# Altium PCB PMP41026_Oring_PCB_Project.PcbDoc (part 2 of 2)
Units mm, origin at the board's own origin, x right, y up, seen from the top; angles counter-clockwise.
Board outline 34.25 x 35.26 mm, 8 copper layers (Top Layer, Layer 2, Layer 3, Layer 4, Layer 5, Layer 6, Layer 7, Bottom Layer), stack 1.271 mm thick; 34 components, 15 nets, 290 pads, 1015 vias.
Unrouted connection lines stored in the file: 1.
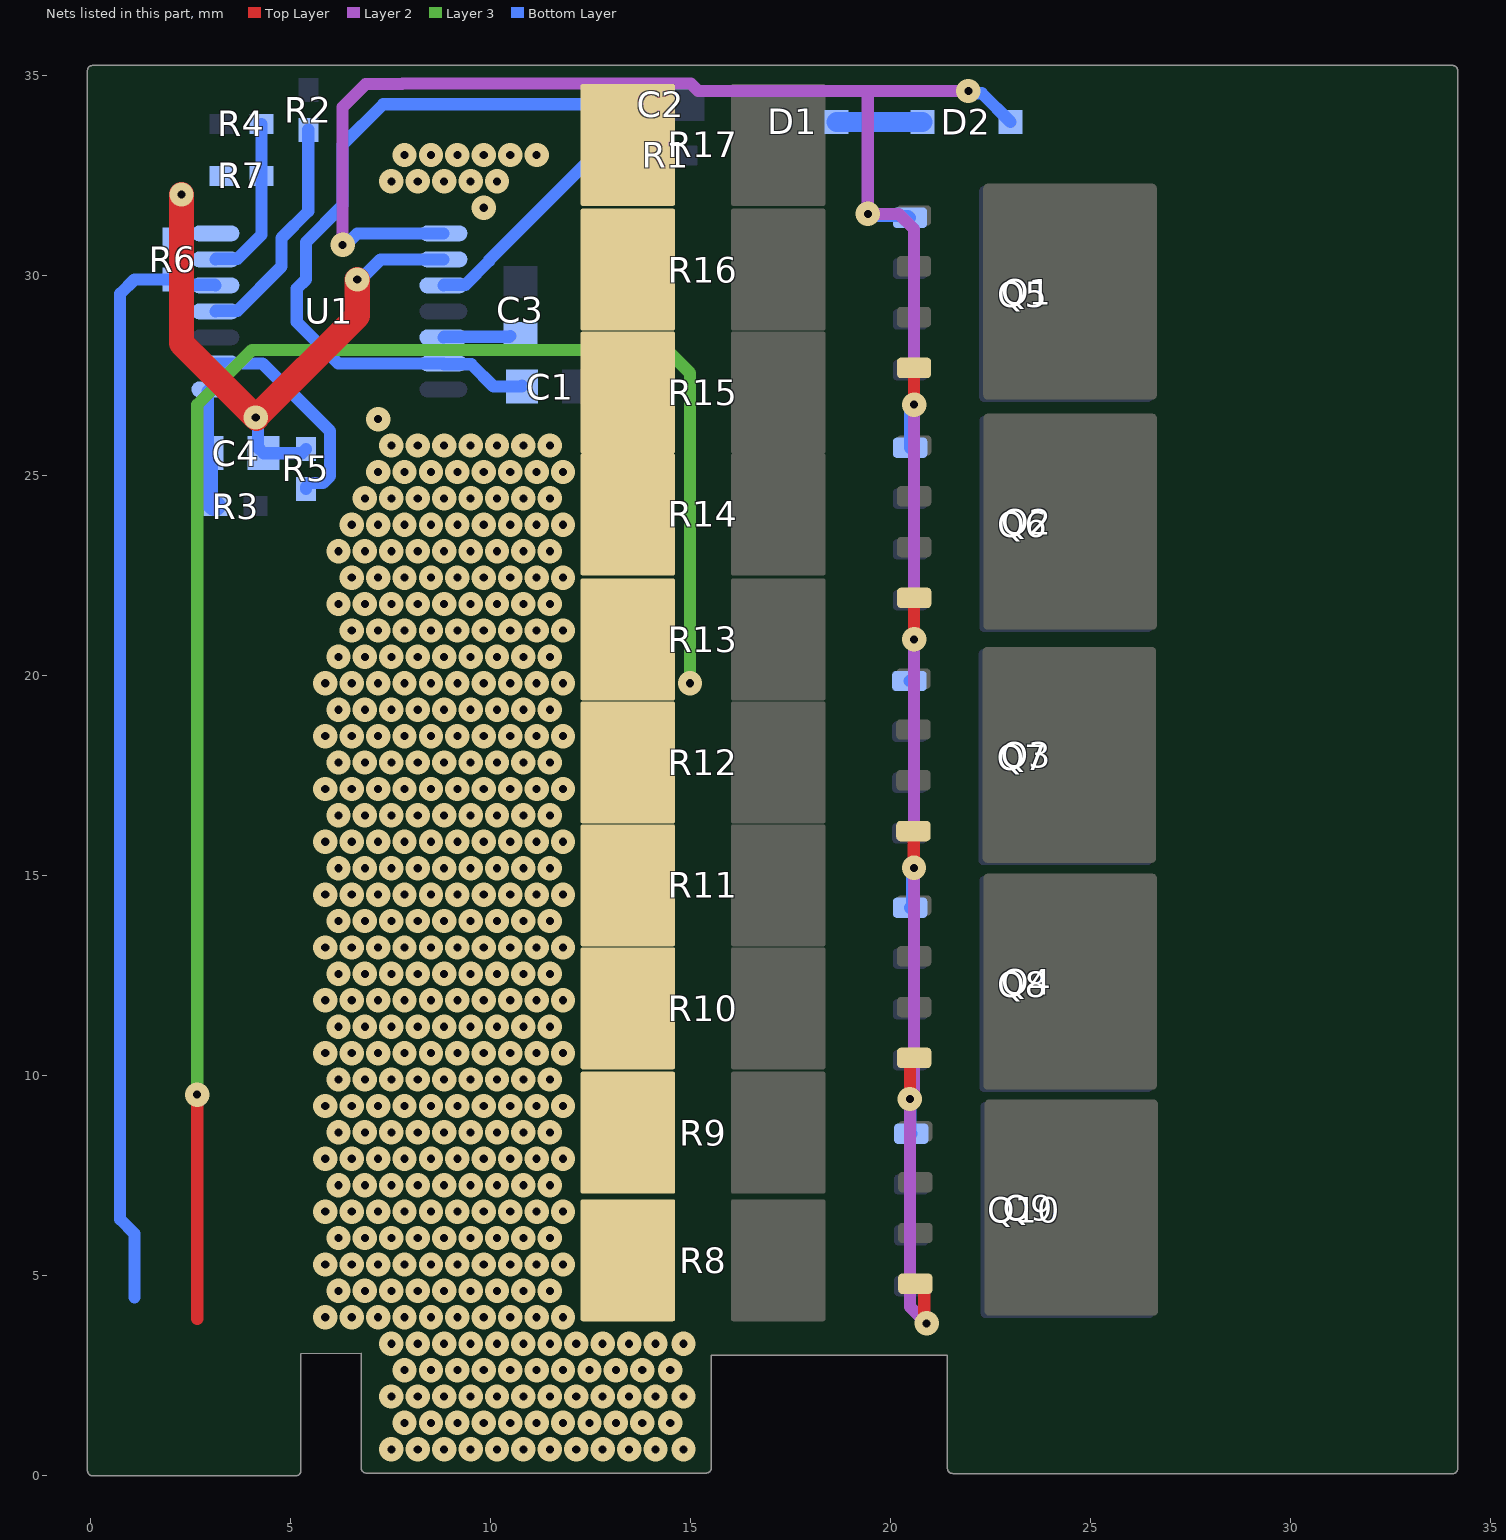
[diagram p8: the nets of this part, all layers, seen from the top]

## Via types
v1: diameter 0.61, hole 0.203, Top Layer to Bottom Layer, 996 vias
v2: diameter 0.61, hole 0.203, Top Layer to Bottom Layer, tented both sides, 18 vias
v3: diameter 0.508, hole 0.254, Top Layer to Bottom Layer, 1 vias

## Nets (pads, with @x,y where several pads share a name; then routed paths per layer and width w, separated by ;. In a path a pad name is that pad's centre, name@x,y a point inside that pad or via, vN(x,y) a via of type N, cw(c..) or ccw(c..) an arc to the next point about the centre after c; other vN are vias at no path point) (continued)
Iout_SNS: R8.1 R9.1 R10.1 R11.1 R12.1 R13.1 R14.1 R15.1 R16.1 R17.1 | length 43.7
  Top Layer w0.305: 2.664,3.927 v2(2.664,9.527)
  Layer 3 w0.305: v2(2.664,9.527) 2.664,26.776 4.035,28.146 14.41,28.146 14.986,27.57 v2(14.986,19.812)
  other v1: 7.518,0.66 8.179,0.66 8.839,0.66 9.5,0.66 10.16,0.66 10.82,0.66 11.481,0.66 12.141,0.66 12.802,0.66 13.462,0.66 14.122,0.66 14.822,0.66 7.849,1.321 8.509,1.321 9.169,1.321 9.83,1.321 10.49,1.321 11.151,1.321 11.811,1.321 12.471,1.321 13.132,1.321 13.792,1.321 14.492,1.321 7.518,1.981 8.179,1.981 8.839,1.981 9.5,1.981 10.16,1.981 10.82,1.981 11.481,1.981 12.141,1.981 12.802,1.981 13.462,1.981 14.122,1.981 14.822,1.981 7.849,2.642 8.509,2.642 9.169,2.642 9.83,2.642 10.49,2.642 11.151,2.642 11.811,2.642 12.471,2.642 13.132,2.642 13.792,2.642 14.492,2.642 7.518,3.302 8.179,3.302 8.839,3.302 9.5,3.302 10.16,3.302 10.82,3.302 11.481,3.302 12.141,3.302 12.802,3.302 13.462,3.302 14.122,3.302 14.822,3.302 5.867,3.962 6.528,3.962 7.188,3.962 7.849,3.962 8.509,3.962 9.169,3.962 9.83,3.962 10.49,3.962 11.151,3.962 11.811,3.962 6.198,4.623 6.858,4.623 7.518,4.623 8.179,4.623 8.839,4.623 9.5,4.623 10.16,4.623 10.82,4.623 11.481,4.623 5.867,5.283 6.528,5.283 7.188,5.283 7.849,5.283 8.509,5.283 9.169,5.283 9.83,5.283 10.49,5.283 11.151,5.283 11.811,5.283 6.198,5.944 6.858,5.944 7.518,5.944 8.179,5.944 8.839,5.944 9.5,5.944 10.16,5.944 10.82,5.944 11.481,5.944 5.867,6.604 6.528,6.604 7.188,6.604 7.849,6.604 8.509,6.604 9.169,6.604 9.83,6.604 10.49,6.604 11.151,6.604 11.811,6.604 6.198,7.264 6.858,7.264 7.518,7.264 8.179,7.264 8.839,7.264 9.5,7.264 10.16,7.264 10.82,7.264 11.481,7.264 5.867,7.925 6.528,7.925 7.188,7.925 7.849,7.925 8.509,7.925 9.169,7.925 9.83,7.925 10.49,7.925 11.151,7.925 11.811,7.925 6.198,8.585 6.858,8.585 7.518,8.585 8.179,8.585 8.839,8.585 9.5,8.585 10.16,8.585 10.82,8.585 11.481,8.585 5.867,9.246 6.528,9.246 7.188,9.246 7.849,9.246 8.509,9.246 9.169,9.246 9.83,9.246 10.49,9.246 11.151,9.246 11.811,9.246 6.198,9.906 6.858,9.906 7.518,9.906 8.179,9.906 8.839,9.906 9.5,9.906 10.16,9.906 10.82,9.906 11.481,9.906 5.867,10.566 6.528,10.566 7.188,10.566 7.849,10.566 8.509,10.566 9.169,10.566 9.83,10.566 10.49,10.566 11.151,10.566 11.811,10.566 6.198,11.227 6.858,11.227 7.518,11.227 8.179,11.227 8.839,11.227 9.5,11.227 10.16,11.227 10.82,11.227 11.481,11.227 5.867,11.887 6.528,11.887 7.188,11.887 7.849,11.887 8.509,11.887 9.169,11.887 9.83,11.887 10.49,11.887 11.151,11.887 11.811,11.887 6.198,12.548 6.858,12.548 7.518,12.548 8.179,12.548 8.839,12.548 9.5,12.548 10.16,12.548 10.82,12.548 11.481,12.548 5.867,13.208 6.528,13.208 7.188,13.208 7.849,13.208 8.509,13.208 9.169,13.208 9.83,13.208 10.49,13.208 11.151,13.208 11.811,13.208 6.198,13.868 6.858,13.868 7.518,13.868 8.179,13.868 8.839,13.868 9.5,13.868 10.16,13.868 10.82,13.868 11.481,13.868 5.867,14.529 6.528,14.529 7.188,14.529 7.849,14.529 8.509,14.529 9.169,14.529 9.83,14.529 10.49,14.529 11.151,14.529 11.811,14.529 6.198,15.189 6.858,15.189 7.518,15.189 8.179,15.189 8.839,15.189 9.5,15.189 10.16,15.189 10.82,15.189 11.481,15.189 5.867,15.85 6.528,15.85 7.188,15.85 7.849,15.85 8.509,15.85 9.169,15.85 9.83,15.85 10.49,15.85 11.151,15.85 11.811,15.85 6.198,16.51 6.858,16.51 7.518,16.51 8.179,16.51 8.839,16.51 9.5,16.51 10.16,16.51 10.82,16.51 11.481,16.51 5.867,17.17 6.528,17.17 7.188,17.17 7.849,17.17 8.509,17.17 9.169,17.17 9.83,17.17 10.49,17.17 11.151,17.17 11.811,17.17 6.198,17.831 6.858,17.831 7.518,17.831 8.179,17.831 8.839,17.831 9.5,17.831 10.16,17.831 10.82,17.831 11.481,17.831 5.867,18.491 6.528,18.491 7.188,18.491 7.849,18.491 8.509,18.491 9.169,18.491 9.83,18.491 10.49,18.491 11.151,18.491 11.811,18.491 6.198,19.152 6.858,19.152 7.518,19.152 8.179,19.152 8.839,19.152 9.5,19.152 10.16,19.152 10.82,19.152 11.481,19.152 5.867,19.812 6.528,19.812 7.188,19.812 7.849,19.812 8.509,19.812 9.169,19.812 9.83,19.812 10.49,19.812 11.151,19.812 11.811,19.812 6.198,20.472 6.858,20.472 7.518,20.472 8.179,20.472 8.839,20.472 9.5,20.472 10.16,20.472 10.82,20.472 11.481,20.472 6.528,21.133 7.188,21.133 7.849,21.133 8.509,21.133 9.169,21.133 9.83,21.133 10.49,21.133 11.151,21.133 11.811,21.133 6.198,21.793 6.858,21.793 7.518,21.793 8.179,21.793 8.839,21.793 9.5,21.793 10.16,21.793 10.82,21.793 11.481,21.793 6.528,22.454 7.188,22.454 7.849,22.454 8.509,22.454 9.169,22.454 9.83,22.454 10.49,22.454 11.151,22.454 11.811,22.454 6.198,23.114 6.858,23.114 7.518,23.114 8.179,23.114 8.839,23.114 9.5,23.114 10.16,23.114 10.82,23.114 11.481,23.114 6.528,23.774 7.188,23.774 7.849,23.774 8.509,23.774 9.169,23.774 9.83,23.774 10.49,23.774 11.151,23.774 11.811,23.774 6.858,24.435 7.518,24.435 8.179,24.435 8.839,24.435 9.5,24.435 10.16,24.435 10.82,24.435 11.481,24.435 7.188,25.095 7.849,25.095 8.509,25.095 9.169,25.095 9.83,25.095 10.49,25.095 11.151,25.095 11.811,25.095 7.518,25.756 8.179,25.756 8.839,25.756 9.5,25.756 10.16,25.756 10.82,25.756 11.481,25.756 7.188,26.416 9.83,31.699 7.518,32.36 8.179,32.36 8.839,32.36 9.5,32.36 10.16,32.36 7.849,33.02 8.509,33.02 9.169,33.02 9.83,33.02 10.49,33.02 11.151,33.02
NetC1_1: C1.1 C2.2 U1.13 | length 18.9
  Bottom Layer w0.305: C1.1@10.785,27.256 C1.1@10.785,27.231 10.073,27.231 9.515,27.79 8.838,27.79 U1.13@8.82,27.808 6.194,27.808 5.156,28.845 5.156,29.681 5.384,29.909 5.384,30.84 6.299,31.756 6.299,33.274 7.315,34.29 C2.2@13.549,34.29
NetC3_2: C3.2 U1.12 | length 1.7
  Bottom Layer w0.305: U1.12@8.82,28.458 8.838,28.476 10.469,28.476 C3.2@10.49,28.497
NetC4_1: C4.1 R3.1 U1.1 | length 3.2
  Bottom Layer w0.305: C4.1@2.928,25.565 2.928,27.114 2.972,27.158 U1.1@3.12,27.158
  Bottom Layer w0.508: C4.1@2.928,25.565 2.928,24.402 3.086,24.244 R3.1@3.128,24.244
NetD1_1: D1.1 D2.1 | length 2.1
  Bottom Layer w0.508: D1.1@18.651,33.845 D2.1@20.795,33.845
NetR1_1: R1.1 U1.10 | length 6.4
  Bottom Layer w0.305: U1.10@8.82,29.758 8.838,29.776 9.37,29.776 9.967,30.373 9.967,30.392 12.582,33.007 R1.1@13.876,33.007
NetR2_1: R2.1 U1.4 | length 5.8
  Bottom Layer w0.305: U1.4@3.12,29.108 3.138,29.126 3.67,29.126 4.775,30.232 4.775,30.945 5.443,31.613 R2.1@5.443,33.65
NetR4_1: R4.1 R7.2 U1.6 | length 4.2
  Bottom Layer w0.305: U1.6@3.12,30.408 3.138,30.426 3.67,30.426 4.27,31.027 R7.2@4.27,32.495 R4.1@4.27,33.795
NetR5_2: R5.2 U1.2 | length 5.5
  Bottom Layer w0.305: U1.2@3.12,27.808 4.296,27.808 5.986,26.117 5.986,24.998 5.808,24.819 5.482,24.819 5.384,24.721 R5.2@5.384,24.671
ORing_CTRL: R6.2 U1.5 | length 27.8
  Bottom Layer w0.305: 1.096,4.465 1.096,6.053 0.739,6.41 0.739,29.551 1.096,29.908 2.014,29.908 2.146,29.776 3.102,29.776 U1.5@3.12,29.758
ORing_Gate: D2.2 Q1.4 Q2.4 Q3.4 Q4.4 Q5.4 Q6.4 Q7.4 Q8.4 Q9.4 Q10.4 U1.8 | length 65.8
  Top Layer w0.305: v2(20.482,9.42) 20.482,10.345 20.585,10.448 Q4.4@20.589,10.448 ; Q3.4@20.571,16.118 20.579,16.11 20.579,15.206 v2(20.586,15.198) ; Q1.4@20.586,27.698 20.587,27.696 20.587,26.78 v2(20.589,26.778) ; v2(20.589,20.909) Q2.4@20.589,21.948 ; Q9.4@20.619,4.799 20.739,4.799 20.841,4.697 20.841,3.868 v2(20.9,3.81)
  Layer 2 w0.305: v2(6.299,30.772) 6.299,34.216 6.874,34.79 7.788,34.79 7.805,34.807 15.002,34.807 15.189,34.62 19.431,34.62 ; v2(20.9,3.81) 20.482,4.228 v2(20.482,9.42) 20.482,9.503 20.586,9.607 v2(20.586,15.198) 20.587,15.2 20.587,20.907 v2(20.589,20.909) v2(20.589,26.778) 20.589,31.161 20.204,31.547 v2(19.431,31.547) 19.431,34.62 ; v2(21.946,34.62) 19.431,34.62
  Bottom Layer w0.305: v2(6.299,30.772) 6.382,30.772 6.668,31.058 U1.8@8.82,31.058 ; v2(19.431,31.547) 19.48,31.498 20.436,31.498 Q5.4@20.484,31.449 ; Q7.4@20.469,19.869 20.486,19.869 20.589,19.972 v2(20.589,20.909) ; v2(20.482,9.42) 20.499,9.403 20.499,8.568 Q10.4@20.517,8.551 ; Q8.4@20.487,14.199 20.537,14.248 20.537,15.149 v2(20.586,15.198) ; Q6.4@20.487,25.699 20.487,26.594 20.589,26.696 v2(20.589,26.778) ; v2(21.946,34.62) 22.004,34.562 22.278,34.562 D2.2@22.995,33.845
SGND: C4.2 R5.1 R6.1 R7.1 U1.7 U1.9 | length 15.4
  Top Layer w0.305: v2@6.61,29.966 v2(6.668,29.908)
  Top Layer w0.635: v2(2.273,32.031) 2.273,28.313 v2(4.128,26.458) ; v2@4.149,26.438 v2(4.128,26.458) ; v2(6.668,29.908) 6.668,28.997 v2(4.128,26.458)
  Bottom Layer w0.305: v2(4.128,26.458) 4.187,26.4 4.187,25.707 C4.2@4.328,25.565 5.286,25.565 5.384,25.662 R5.1@5.384,25.671 ; v2(6.668,29.908) 6.745,29.908 7.245,30.408 U1.9@8.82,30.408
pads on no net: Q1.9@22.576,27.23 Q1.9@22.576,31.975 Q1.9@22.871,28.273 Q1.9@22.871,29.603 Q1.9@22.871,30.933 Q1.9@24.021,28.273 Q1.9@24.021,29.603 Q1.9@24.021,30.933 Q1.9@24.156,29.603 Q1.9@25.171,28.273 Q1.9@25.171,29.603 Q1.9@25.171,30.933 Q2.9@22.579,21.48 Q2.9@22.579,26.225 Q2.9@22.874,22.523 Q2.9@22.874,23.853 Q2.9@22.874,25.183 Q2.9@24.024,22.523 Q2.9@24.024,23.853 Q2.9@24.024,25.183 Q2.9@24.159,23.853 Q2.9@25.174,22.523 Q2.9@25.174,23.853 Q2.9@25.174,25.183 Q3.9@22.561,15.65 Q3.9@22.561,20.395 Q3.9@22.856,16.693 Q3.9@22.856,18.023 Q3.9@22.856,19.353 Q3.9@24.006,16.693 Q3.9@24.006,18.023 Q3.9@24.006,19.353 Q3.9@24.141,18.023 Q3.9@25.156,16.693 Q3.9@25.156,18.023 Q3.9@25.156,19.353 Q4.9@22.579,9.98 Q4.9@22.579,14.725 Q4.9@22.874,11.023 Q4.9@22.874,12.353 Q4.9@22.874,13.683 Q4.9@24.024,11.023 Q4.9@24.024,12.353 Q4.9@24.024,13.683 Q4.9@24.159,12.353 Q4.9@25.174,11.023 Q4.9@25.174,12.353 Q4.9@25.174,13.683 Q5.9@22.474,27.172 Q5.9@22.474,31.917 Q5.9@22.769,28.214 Q5.9@22.769,29.544 Q5.9@22.769,30.874 Q5.9@23.919,28.214 Q5.9@23.919,29.544 Q5.9@23.919,30.874 Q5.9@24.054,29.544 Q5.9@25.069,28.214 Q5.9@25.069,29.544 Q5.9@25.069,30.874 Q6.9@22.477,21.422 Q6.9@22.477,26.167 Q6.9@22.772,22.464 Q6.9@22.772,23.794 Q6.9@22.772,25.124 Q6.9@23.922,22.464 Q6.9@23.922,23.794 Q6.9@23.922,25.124 Q6.9@24.057,23.794 Q6.9@25.072,22.464 Q6.9@25.072,23.794 Q6.9@25.072,25.124 Q7.9@22.459,15.592 Q7.9@22.459,20.337 Q7.9@22.754,16.634 Q7.9@22.754,17.964 Q7.9@22.754,19.294 Q7.9@23.904,16.634 Q7.9@23.904,17.964 Q7.9@23.904,19.294 Q7.9@24.039,17.964 Q7.9@25.054,16.634 Q7.9@25.054,17.964 Q7.9@25.054,19.294 Q8.9@22.477,9.922 Q8.9@22.477,14.667 Q8.9@22.772,10.964 Q8.9@22.772,12.294 Q8.9@22.772,13.624 Q8.9@23.922,10.964 Q8.9@23.922,12.294 Q8.9@23.922,13.624 Q8.9@24.057,12.294 Q8.9@25.072,10.964 Q8.9@25.072,12.294 Q8.9@25.072,13.624 Q9.9@22.609,4.332 Q9.9@22.609,9.077 Q9.9@22.904,5.374 Q9.9@22.904,6.704 Q9.9@22.904,8.034 Q9.9@24.054,5.374 Q9.9@24.054,6.704 Q9.9@24.054,8.034 Q9.9@24.189,6.704 Q9.9@25.204,5.374 Q9.9@25.204,6.704 Q9.9@25.204,8.034 Q10.9@22.507,4.273 Q10.9@22.507,9.018 Q10.9@22.802,5.316 Q10.9@22.802,6.646 Q10.9@22.802,7.976 Q10.9@23.952,5.316 Q10.9@23.952,6.646 Q10.9@23.952,7.976 Q10.9@24.087,6.646 Q10.9@25.102,5.316 Q10.9@25.102,6.646 Q10.9@25.102,7.976 U1.3 U1.14

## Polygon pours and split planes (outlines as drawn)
SGND on Layer 5 "SGND" (solid, remove dead copper, pour order 85): 1.27,32.512 0.254,31.496 0.254,13.112 3.649,9.718 3.649,5.072 4.149,4.572 4.395,4.572 4.649,4.826 4.649,26.388 7.091,28.83 7.091,29.966 6.991,29.966 4.445,32.512
Iout_SNS on Layer 5 "LAYER_5_IOUT_SNS_P055" (solid, remove dead copper, pour order 55): 14.904,3.658 15.426,3.136 15.5,3.136 15.5,0.185 15.49,0.195 13,0.16 6.891,0.2 6.891,3.187 5.131,3.187 5.131,34.738 5.523,35.13 14.904,35.13 14.904,20.574 14.471,20.141 14.471,19.483 14.904,19.05
12VB on Layer 5 "LAYER_5_12VB_P069" (solid, remove dead copper, pour order 69): 21.946,3.946 21.5,3.5 21.5,0.249 21.588,0.16 24.33,0.185 34.049,0.185 34.049,33.089 32.049,35.089 21.946,35.13
12VA on Layer 5 "LAYER_5_12VA_P074" (solid, remove dead copper, pour order 74): 15.57,4.066 16.5,3.152 21.256,3.148 21.26,3.683 21.209,3.734 21.285,3.81 21.285,35.126 15.57,35.179 15.57,19.812 16.153,19.229 16.153,18.617 15.57,18.034
no net on Top Solder "NONET_L-01_P-001" (solid): 6.891,3.211 6.891,0.2 15.391,0.145 15.391,3.185
no net on Top Solder "NONET_L-01_P-001" (solid): 21.549,3.324 21.549,0.185 32.065,0.185 32.034,3.324
no net on Top Solder "NONET_L-01_P-001" (solid): 0.049,3.187 5.105,3.187 5.105,0.197 5.131,0.171 0.049,0.171
no net on Top Solder "NONET_L-01_P-001" (solid): 7.518,35.13 7.518,24.645 5.131,22.258 5.131,4.06 6.07,3.121 6.891,3.121 6.891,0.197 6.941,0.146 14.561,0.146 14.561,3.708 12.167,3.708 12.141,3.683 12.116,3.708 12.116,35.179
no net on Top Solder "NONET_L-01_P-001" (solid): 23.038,32.563 23.241,32.36 27,32.36 27,3.324 26.811,3.135 24.018,3.135 24.018,0.178 34.049,0.187 34.049,33.089 32.008,35.13 23.038,35.13
SGND on Bottom Layer "BOTTOM_LAYER_SGND_P041" (solid, remove dead copper, pour order 41): 1.391,30.539 1.4,30.53 3.774,30.53 3.774,33.053 3.75,33.077 1.905,33.077 1.391,32.563
Iout_SNS on Bottom Layer "BOTTOM_LAYER_IOUT_SNS_P058" (solid, remove dead copper, pour order 58): 14.904,3.888 15.391,3.4 15.391,0.237 15.302,0.147 14.471,0.147 6.891,0.197 6.891,3.184 5.131,3.184 5.131,26.092 14.904,26.092 14.904,20.574 14.308,19.978 14.308,19.122 14.904,18.525
12VA on Bottom Layer "BOTTOM_LAYER_12VA_P077" (solid, remove dead copper, pour order 77): 15.57,4.066 16.5,3.152 21.256,3.148 21.26,3.683 21.209,3.734 21.285,3.81 21.285,35.126 15.57,35.179 15.57,19.812 16.122,19.26 16.122,18.798 15.57,18.246
12VB on Bottom Layer "BOTTOM_LAYER_12VB_P072" (solid, remove dead copper, pour order 72): 21.946,3.946 21.5,3.5 21.5,0.211 21.565,0.146 21.615,0.197 24.3,0.185 34.049,0.185 34.049,33.089 32.049,35.089 21.946,35.13
SGND on Layer 6 "SGND" (solid, remove dead copper, pour order 83): 1.27,32.512 0.254,31.496 0.254,13.112 3.649,9.718 3.649,5.072 4.149,4.572 4.395,4.572 4.649,4.826 4.649,26.388 7.091,28.83 7.091,29.966 6.991,29.966 4.445,32.512
Iout_SNS on Layer 6 "LAYER_6_IOUT_SNS_P056" (solid, remove dead copper, pour order 56): 14.904,3.732 15.5,3.136 15.5,0.411 15.24,0.151 14.471,0.151 6.891,0.2 6.891,3.187 5.131,3.187 5.131,34.738 5.523,35.13 14.904,35.13 14.904,20.574 14.521,20.191 14.521,19.433 14.904,19.05
12VB on Layer 6 "LAYER_6_12VB_P070" (solid, remove dead copper, pour order 70): 21.946,4.6 21.5,4.154 21.5,0.185 21.503,0.183 24.5,0.185 34.049,0.185 34.049,33.089 32.049,35.089 21.946,35.13
12VA on Layer 6 "LAYER_6_12VA_P075" (solid, remove dead copper, pour order 75): 16.5,3.152 15.57,4.082 15.57,18.034 16.256,18.72 16.256,19.229 15.57,19.915 15.57,35.179 21.285,35.126 21.285,3.81 21.209,3.734 21.26,3.683 21.256,3.148
no net on Bottom Solder "NONET_L-01_P-001" (solid): 0.049,3.187 5.131,3.187 5.131,0.171 0.049,0.171
no net on Bottom Solder "NONET_L-01_P-001" (solid): 0.102,5.639 4.801,5.639 4.801,2.669 4.828,2.642 4.438,2.252 0.049,2.252
no net on Bottom Solder "NONET_L-01_P-001" (solid): 6.891,3.211 6.891,0.2 15.391,0.145 15.391,3.185
no net on Bottom Solder "NONET_L-01_P-001" (solid): 21.549,3.324 21.549,0.185 32.065,0.185 32.034,3.324
no net on Bottom Solder "NONET_L-01_P-001" (solid): 7.518,26.149 7.518,24.739 5.131,22.351 5.131,4.154 6.07,3.215 6.891,3.215 6.891,0.29 6.941,0.24 14.561,0.24 14.561,3.802 14.561,26.224
no net on Bottom Solder "NONET_L-01_P-001" (solid): 24.049,32.457 27.03,32.457 27.03,3.422 26.841,3.233 24.049,3.233 24.049,0.276 34.049,0.285 34.049,33.217 32.038,35.228 24.049,35.228
no net on Bottom Solder "NONET_L-01_P-001" (solid): 15.57,30.772 15.57,3.136 15.586,3.121 19.736,3.121 19.736,30.772
SGND on Top Layer "SGND" (solid, remove dead copper, pour order 79): 1.27,32.512 0.254,31.496 0.254,13.112 3.649,9.718 3.649,2.286 4.649,2.286 4.649,26.388 7.091,28.83 7.091,29.966 6.991,29.966 4.445,32.512
Iout_SNS on Top Layer "TOP_LAYER_IOUT_SNS_P051" (solid, remove dead copper, pour order 51): 6.891,0.2 15.391,0.195 15.391,3.212 14.904,3.693 14.904,35.13 5.523,35.13 5.131,34.738 5.131,3.187 6.891,3.187
12VA on Top Layer "TOP_LAYER_12VA_P059" (solid, remove dead copper, pour order 59): 15.57,4.089 16.5,3.151 20.616,3.141 21.285,3.81 21.285,35.126 15.57,35.179
12VB on Top Layer "TOP_LAYER_12VB_P063" (solid, remove dead copper, pour order 63): 21.946,4.623 21.549,4.227 21.549,0.184 21.551,0.183 24.359,0.185 34.049,0.185 34.049,33.089 32.049,35.089 21.946,35.13
Iout_SNS on Layer 2 "LAYER_2_IOUT_SNS_P052" (solid, remove dead copper, pour order 52): 14.904,20.574 14.471,20.141 14.471,19.455 14.904,19.022 14.904,18.838 14.904,3.836 15.391,3.349 15.391,0.145 6.891,0.2 6.891,3.187 5.131,3.187 4.509,3.81 0.508,3.81 0.254,4.064 0.254,28.217 0.993,28.956 5.131,28.954 5.131,34.738 5.523,35.13 14.904,35.13
12VA on Layer 2 "LAYER_2_12VA_P062" (solid, remove dead copper, pour order 62): 15.57,4.066 16.5,3.152 21.256,3.148 21.26,3.683 21.209,3.734 21.285,3.81 21.285,35.126 15.57,35.179 15.57,19.812 16.256,19.126 16.256,18.796 15.582,18.122 15.57,18.034
12VB on Layer 2 "LAYER_2_12VB_P066" (solid, remove dead copper, pour order 66): 21.946,4.623 21.5,4.177 21.5,0.234 21.551,0.183 24.5,0.185 34.049,0.185 34.049,33.089 32.049,35.089 21.946,35.13
Iout_SNS on Layer 3 "LAYER_3_IOUT_SNS_P053" (solid, remove dead copper, pour order 53): 14.561,4.161 15.391,3.331 15.391,0.24 15.346,0.195 13,0.16 6.891,0.2 6.891,3.187 5.131,3.187 5.131,27.61 14.561,27.61
12VA on Layer 3 "LAYER_3_12VA_P064" (solid, remove dead copper, pour order 64): 15.57,4.088 16.527,3.131 17,3.151 21.256,3.148 21.26,3.683 21.209,3.734 21.285,3.81 21.285,35.126 16.256,35.173 16.256,19.229 16.256,18.508 15.57,17.822
12VB on Layer 3 "LAYER_3_12VB_P067" (solid, remove dead copper, pour order 67): 21.946,3.946 21.5,3.5 21.5,0.185 21.515,0.2 24.33,0.185 34.049,0.185 34.049,33.089 32.049,35.089 21.946,35.13
Iout_SNS on Layer 4 "LAYER_4_IOUT_SNS_P054" (solid, remove dead copper, pour order 54): 14.904,3.745 15.5,3.149 15.5,0.151 14.471,0.151 6.891,0.2 6.891,3.187 5.131,3.187 5.131,3.251 4.572,3.81 0.508,3.81 0.254,4.064 0.254,28.194 1.016,28.956 5.131,28.956 5.131,34.738 5.523,35.13 14.904,35.13 14.904,20.499 14.471,20.066 14.478,20.059 14.478,19.264 14.904,18.838
12VB on Layer 4 "LAYER_4_12VB_P068" (solid, remove dead copper, pour order 68): 21.946,4.38 21.5,3.934 21.5,0.235 21.552,0.183 24.5,0.185 34.049,0.185 34.049,33.089 32.049,35.089 21.946,35.13
12VA on Layer 4 "LAYER_4_12VA_P073" (solid, remove dead copper, pour order 73): 15.57,4.022 15.614,4.022 16.5,3.152 21.256,3.148 21.26,3.683 21.209,3.734 21.285,3.81 21.285,35.126 15.57,35.179 15.57,19.812 16.256,19.126 16.256,18.72 15.57,18.034
SGND on Layer 7 "SGND" (solid, remove dead copper, pour order 81): 1.27,32.512 0.254,31.496 0.254,13.112 3.649,9.718 3.649,5.072 4.149,4.572 4.395,4.572 4.649,4.826 4.649,26.388 7.091,28.83 7.091,29.966 6.991,29.966 4.445,32.512
Iout_SNS on Layer 7 "LAYER_7_IOUT_SNS_P057" (solid, remove dead copper, pour order 57): 14.904,3.658 15.391,3.171 15.391,0.24 15.302,0.151 14.5,0.151 6.891,0.2 6.891,3.187 5.131,3.187 5.131,34.738 5.523,35.13 14.904,35.13 14.904,20.574 14.471,20.141 14.471,19.454 14.904,19.05
12VB on Layer 7 "LAYER_7_12VB_P071" (solid, remove dead copper, pour order 71): 21.914,3.815 21.5,3.4 21.5,0.178 21.505,0.183 24.33,0.178 34.049,0.178 34.049,33.05 32.018,35.081 21.914,35.123
12VA on Layer 7 "LAYER_7_12VA_P076" (solid, remove dead copper, pour order 76): 15.57,4.022 15.614,4.022 16.5,3.152 21.256,3.148 21.26,3.683 21.209,3.734 21.285,3.81 21.285,35.126 15.57,35.179 15.57,19.812 16.153,19.229 16.153,18.617 15.57,18.034

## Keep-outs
Keep-Out Layer:
  text ".Layer_Name" at 14.656,-21.806 h1.52

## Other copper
Top Layer:
  region net Iout_SNS: 3.074,5.148 2.774,5.448 2.374,5.448 2.074,5.148 2.074,0.148 3.074,0.148
  region net SGND: 4.649,5.123 4.349,5.423 3.949,5.423 3.649,5.123 3.649,0.123 4.649,0.123
  region net 12VA: 1.541,5.136 1.241,5.436 0.841,5.436 0.541,5.136 0.541,0.136 1.541,0.136
  text ".Layer_Name" at 14.656,-21.806 h1.52
Bottom Layer:
  region net 12VS: 2.059,5.148 2.359,5.448 2.759,5.448 3.059,5.148 3.059,0.148 2.059,0.148
  region net SGND: 3.638,5.146 3.938,5.446 4.338,5.446 4.638,5.146 4.638,0.146 3.638,0.146
  region net ORing_CTRL: 0.541,5.148 0.841,5.448 1.241,5.448 1.541,5.148 1.541,0.148 0.541,0.148
  text ".Layer_Name" at 14.656,-21.806 h1.52

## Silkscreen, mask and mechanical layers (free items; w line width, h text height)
Top Overlay:
  text ".Layer_Name" at 14.656,-21.806 h1.52
Bottom Overlay:
  text "ORING DC" at 0.596,6.299 h2.03 r270
  text "PMP41026 RevA" at 2.374,6.299 h2.03 r270
  text ".Layer_Name" at 14.656,-21.806 h1.52
Top Paste:
  text ".Layer_Name" at 14.656,-21.806 h1.52
Bottom Paste:
  text ".Layer_Name" at 14.656,-21.806 h1.52
Top Solder:
  text ".Layer_Name" at 14.656,-21.806 h1.52
  text ".Layer_Name" at 14.656,-21.806 h1.52
Bottom Solder:
  text ".Layer_Name" at 14.656,-21.806 h1.52
Drill Guide:
  text ".Layer_Name" at 14.656,-21.806 h1.52
M1 Board Outline:
  lines w0.254: 5.131,0.127 0.049,0.127 0.049,35.13 34.049,35.13 34.049,0.178 21.549,0.184 21.549,3.136 ; 5.131,0.178 5.131,3.178 ; 5.131,3.181 6.883,3.187 ; 6.891,3.195 6.891,0.195 15.391,0.195 ; 15.391,0.202 15.391,3.136 21.549,3.136 ; 21.549,3.136 21.549,3.136
  text ".Layer_Name" at 14.656,-21.806 h1.52
M2 Board Dimensions:
  rectangle: 3.175,-10.16 12.7,-6.985
  rectangle: 0,-6.985 3.175,-3.81
  lines w0.178: 0,-6.985 25.4,-6.985 ; 3.175,-10.16 3.175,-3.81 ; 6.35,-10.16 6.35,-3.81 ; 12.7,-10.16 12.7,-3.81 ; 19.05,-10.16 19.05,-3.81 ; 0,-10.16 0,-3.81 25.4,-3.81 25.4,-10.16 0,-10.16
  text ".Layer_Name" at 14.656,-21.806 h1.52
M3 3D STEP Top:
  text ".Layer_Name" at 14.656,-21.806 h1.52
M4 3D STEP Bottom:
  text ".Layer_Name" at 14.656,-21.806 h1.52
M5 Assembly Top:
  lines w0.254: -7.417,-23.626 160.223,-23.626 ; -7.417,-18.462 160.274,-18.462 ; -7.417,-13.297 -7.417,-28.791 94.31,-28.791 160.274,-28.791 160.274,-13.297 -7.404,-13.297 -7.404,-28.791 32.614,-28.791 ; 55.194,-28.791 55.194,-13.297 ; 87.376,-18.462 87.376,-13.297 ; 108.712,-18.462 108.712,-13.297 ; 124.511,-28.956 124.511,-23.804
  text "COMPONENTS MARKED 'DNP' SHOULD NOT BE POPULATED." at 29.299,-8.09 h1.52
  text "ASSEMBLY VARIANT:" at 29.286,-11.024 h1.52
  text ".VariantName" at 55.601,-11.024 h1.52
  text "PCB VIEWED FROM TOP SIDE" at -5.804,-16.654 h1.52
  text "BOARD #:" at 57.099,-16.654 h1.52
  text ".PRJ_Number" at 70.955,-16.654 h1.52
  text "REV:" at 92.405,-16.654 h1.52
  text ".PCB_Rev" at 99.809,-16.654 h1.52
  text "SVN REV:" at 113.69,-16.654 h1.52
  text ".VersionControl_RevNumber" at 126.543,-16.654 h1.52
  text "TID #:" at 57.099,-21.819 h1.52
  text ".TID" at 70.955,-21.819 h1.52
  text "PLOT NAME =" at -5.804,-27.034 h1.52
  text ".plot_File_Name" at 14.656,-27.034 h1.52
  text "GENERATED    :" at 57.15,-27.034 h1.52
  text ".Print_Date" at 79.235,-27.034 h1.52
  text ".Print_Time" at 97.752,-27.034 h1.52
  text "TEXAS INSTRUMENTS" at 129.87,-27.034 h1.52
M6 Assembly Bottom:
  lines w0.254: -7.429,-18.474 160.261,-18.474 ; -7.379,-23.639 160.261,-23.639 ; 28.334,-28.969 28.334,-23.817 ; 44.133,-18.474 44.133,-13.31 ; 65.468,-18.474 65.468,-13.31 ; 97.65,-28.804 97.65,-13.31 ; 120.231,-28.804 160.249,-28.804 160.249,-13.31 -7.429,-13.31 -7.429,-28.804 58.534,-28.804 160.261,-28.804 160.261,-13.31
  text "COMPONENTS MARKED 'DNP' SHOULD NOT BE POPULATED." at 154.991,-8.077 h1.52
  text ".VariantName" at 128.473,-11.024 h1.52
  text "ASSEMBLY VARIANT:" at 154.864,-11.024 h1.52
  text ".VersionControl_RevNumber" at 26.302,-16.667 h1.52
  text "SVN REV:" at 39.154,-16.667 h1.52
  text ".PCB_Rev" at 53.035,-16.667 h1.52
  text "REV:" at 60.439,-16.667 h1.52
  text ".PRJ_Number" at 81.89,-16.667 h1.52
  text "BOARD #:" at 95.745,-16.667 h1.52
  text "PCB VIEWED FROM BOTTOM SIDE" at 158.648,-16.667 h1.52
  text ".TID" at 81.89,-21.831 h1.52
  text "TID #:" at 95.745,-21.831 h1.52
  text "TEXAS INSTRUMENTS" at 22.974,-27.047 h1.52
  text ".Print_Time" at 55.093,-27.047 h1.52
  text ".Print_Date" at 73.609,-27.047 h1.52
  text "GENERATED    :" at 95.694,-27.047 h1.52
  text ".plot_File_Name" at 138.189,-27.047 h1.52
  text "PLOT NAME =" at 158.648,-27.047 h1.52
M9 Title Sheet:
  drawing of 57 lines, arcs and shapes, not listed
  text "1" at 18.792,204.127 h1.78
  text "2" at 82.182,204.127 h1.78
  text "3" at 145.411,204.127 h1.78
  text "4" at 209.08,204.127 h1.78
  text "5" at 272.555,204.127 h1.78
  text "6" at 336.182,204.127 h1.78
  text "A" at -10.579,175.095 h1.78
  text "A" at 365.341,175.095 h1.78
  text "B" at -10.579,114.643 h1.78
  text "B" at 365.341,114.643 h1.78
  text "C" at -10.579,54.318 h1.78
  text "C" at 365.341,54.318 h1.78
  text "PROJECT TITLE:" at 288.125,7.048 h1.14
  text ".PRJ_Title" at 289.395,3.662 h1.78
  text "DESIGNED FOR:" at 288.125,-0.597 h1.14
  text ".PRJ_Customer" at 289.395,-4.153 h1.78
  text "D" at -10.579,-5.88 h1.78
  text "D" at 365.341,-5.88 h1.78
  text "FILE NAME:" at 288.125,-8.217 h1.14
  text ".PCB_File_Name_No_Path" at 289.395,-11.265 h1.78
  text "Texas Instruments (TI) and/or its licensors do not warrant the accuracy or completeness of this specification" at 161.9,-15.376 h1.14
  text "ENGINEER:" at 288.125,-15.583 h1.14
  text "LAYOUT BY:" at 326.352,-15.583 h1.14
  text "or any information contained therein. TI and/or its licensors do not warrant that this design will meet" at 160.757,-18.237 h1.14
  text ".PRJ_Engineer" at 289.395,-19.52 h1.78
  text ".PCB_Layout" at 327.635,-19.52 h1.78
  text "the specifications, will be suitable for your application or fit for any particular purpose, or will operate in" at 160.757,-21.099 h1.14
  text ".Layer_Name" at 14.656,-21.806 h1.52
  text "ALTIUM DESIGNER VERSION:" at 326.352,-23.457 h1.14
  text "an implementation. TI and/or its licensors do not warrant that the design is production worthy. You should" at 160.757,-23.961 h1.14
  text "completely validate and test your design implementation to confirm the system functionality for your application." at 161.9,-26.822 h1.14
  text ".print_Scale" at 289.395,-26.843 h1.78
  text ".Application_BuildNumber" at 327.635,-26.843 h1.78
  text "1" at 18.792,-32.093 h1.78
  text "2" at 82.182,-32.093 h1.78
  text "3" at 145.411,-32.093 h1.78
  text "4" at 209.08,-32.093 h1.78
  text "5" at 272.555,-32.093 h1.78
  text "6" at 336.182,-32.093 h1.78
M10 Fab Notes:
  drawing of 189 lines, arcs and shapes, not listed
  text "DESIGN INFORMATION" at 314.503,161.447 h1.52
  text "MIN. TRACK WIDTH:" at 298.131,158.091 h1.52
  text "8" at 325.976,158.091 h1.52
  text "MIL" at 329.907,158.091 h1.52
  text "7.874" at 321.75,155 h1.52
  text "MIN. CLEARANCE:" at 298.131,154.938 h1.52
  text "MIL" at 329.907,154.938 h1.52
  text "MIN. VIA PAD SIZE:" at 298.131,151.785 h1.52
  text "24" at 325.214,151.785 h1.52
  text "MIL" at 329.907,151.785 h1.52
  text "0.05mm (2MIL)" at 315.784,148.486 h1.52
  text "MINIMUM ANNULAR RING" at 289.769,148.277 h1.52
  text "EXTERNAL" at 333.768,148.277 h1.52
  text "PER" at 294.849,145.48 h1.52
  text "IPC-D-275 CLASS 2 LEVEL C" at 300.437,145.48 h1.52
  text "MIL, HOLES" at 338.238,142.928 h1.52
  text "+/-" at 328.27,142.709 h1.52
  text "+/-" at 349.961,142.709 h1.52
  text "REGISTRATION TOLERANCES:" at 289.769,142.682 h1.52
  text "METAL" at 320.243,142.682 h1.52
  text "5" at 334.879,142.683 h1.52
  text "3" at 356.037,142.683 h1.52
  text "MIL" at 358.99,142.682 h1.52
  text "HOLE SIZE TOLERANCE (UNLESS OTHERWISE SPECIFIED):" at 289.769,140.185 h1.52
  text "+/-" at 349.961,140.112 h1.52
  text "3" at 356.037,140.085 h1.52
  text "MIL" at 358.99,140.085 h1.52
  text "MATERIAL:" at 287.87,136.589 h1.52
  text "FR-4 High Tg" at 312.926,133.324 h1.52
  text "X" at 309.257,133.122 h1.52
  text "FR-408" at 298.563,133.007 h1.52
  text "OTHER" at 336.358,133.007 h1.52
  text "62 MIL (1.6mm) +/-10%" at 306.694,129.374 h1.52
  text "X" at 303.643,129.312 h1.52
  text "THICKNESS:" at 289.769,129.165 h1.52
  text "OTHER" at 339.33,129.165 h1.52
  text "TOLERANCE:" at 289.769,125.652 h1.52
  text "X" at 311.314,125.652 h1.52
  text "ANSI IPC-6012 TYPE 3 CLASS 2" at 315.836,125.652 h1.52
  text "OTHER +/-" at 315.835,121.989 h1.52
  text "BOW & TWIST:" at 289.769,118.302 h1.52
  text "X" at 311.314,118.302 h1.52
  text "ANSI IPC-6012 TYPE 3 CLASS 2" at 315.836,118.302 h1.52
  text "OTHER +/-" at 315.835,114.576 h1.52
  text "DRILLING:" at 287.87,111.258 h1.52
  text "NC_DRILL FILES" at 332.599,108.586 h1.52
  text "REFERENCE:" at 289.769,108.486 h1.52
  text "X" at 306.463,108.484 h1.52
  text "AS SHOWN" at 310.984,108.486 h1.52
  text "X" at 329.348,108.486 h1.52
  text "OTHER" at 340.168,104.873 h1.52
  text "PTH COPPER THICKNESS:" at 289.761,104.783 h1.52
  text "X" at 318.697,104.783 h1.52
  text "20-30 um" at 321.948,104.783 h1.52
  text "BOARD FINISH:" at 287.87,101.034 h1.52
  text "SILKSCREEN:" at 291.812,98.237 h1.52
  text "X" at 316.14,98.237 h1.52
  text "TOP" at 319.112,98.237 h1.52
  text "X" at 329.094,98.237 h1.52
  text "BOTTOM" at 332.091,98.237 h1.52
  text "SILKSCREEN COLOR:" at 291.812,94.295 h1.52
  text "X" at 316.115,94.295 h1.52
  text "WHITE" at 319.112,94.295 h1.52
  text "OTHER" at 332.091,94.295 h1.52
  text "X" at 319.442,90.652 h1.52
  text "GREEN" at 322.439,90.652 h1.52
  text "OTHER" at 338.136,90.652 h1.52
  text "SOLDER RESIST COLOR:" at 291.812,90.477 h1.52
  text "X" at 319.442,86.734 h1.52
  text "MATTE" at 322.439,86.734 h1.52
  text "SEMI-GLOSS" at 338.125,86.717 h1.52
  text "IMMERSION GOLD (ENIG)" at 314.819,82.345 h1.52
  text "ENEPIG" at 348.793,82.162 h1.52
  text "SURFACE FINISH:" at 287.87,82.136 h1.52
  text "X" at 310.298,82.136 h1.52
  text "IMM. TIN/SILVER OR EQUIV" at 296.24,78.649 h1.52
  text "OTHER" at 332.599,78.549 h1.52
  text "ARRAY/PANEL:" at 287.87,74.602 h1.52
  text "CUT AND TRIM PER M1 BOARD OUTLINE" at 314.819,74.393 h1.52
  text "N.C. ROUTE" at 314.819,70.94 h1.52
  text "X" at 332.295,70.94 h1.52
  text "V. SCORE" at 336.816,70.94 h1.52
  text "CERTIFICATION:" at 287.87,67.66 h1.52
  text "MATERIALS AND WORKMANSHIP FOR ALL PCBS" at 306.285,67.66 h1.52
  text "TO MEET OR EXCEED THE REQUIREMENTS OF:" at 306.285,65.271 h1.52
  text "X" at 297.078,62.003 h1.52
  text "ANSI IPC-A-600F CLASS ->" at 300.329,62.003 h1.52
  text "X" at 342.188,62.003 h1.52
  text "2" at 344.982,62.003 h1.52
  text "1" at 336.981,61.965 h1.52
  text "3" at 353.973,61.965 h1.52
  text "X" at 317.702,58.252 h1.52
  text "RoHS" at 320.953,58.252 h1.52
  text "OTHER" at 337.321,58.252 h1.52
  text "PER ORDER" at 347.407,58.252 h1.52
  text "ALL BOARDS MUST MEET OR EXCEED UL94-V0 REQUIREMENTS." at 288.569,54.345 h1.52
  text "PCB MUST BEAR THE UL94V-0 UL REGISTERED MATERIAL ID NUMBER" at 288.569,51.397 h1.52
  text "ADDITIONAL REQUIREMENTS:" at 287.87,47.094 h1.52
  text "MICROSECTION:" at 289.769,44.373 h1.52
  text "YES" at 312.775,44.373 h1.52
  text "REQUIRED" at 334.657,40.707 h1.52
  text "BARE BOARD ELEC. TEST:" at 289.769,40.634 h1.52
  text "NONE" at 322.935,40.634 h1.52
  text "X" at 331.66,40.634 h1.52
  text "PER ORDER" at 349.693,40.634 h1.52
  text "XX MIL VIAS REQUIRE NON-CONDUCTIVE FILL AND PLANARIZE" at 294.04,35.428 h1.5
  text "XX MIL VIAS REQUIRE CONDUCTIVE FILL AND PLANARIZE" at 294.243,32.787 h1.52
  text "OUTER XX MIL TRACES REQUIRE 50 OHM SINGLE-ENDED IMPEDANCE" at 294.218,28.637 h1.47
  text "LAYER 2 & 3 (INNER LAYERS) XX MIL WIDE, XX MIL SPACE / TRACES REQUIRE 100 OHM DIFFERENTIAL IMPEDANCE" at 294.015,22.65 h1.52
  text ".Layer_Name" at 14.656,-21.806 h1.52
M11 Gerber Information:
  lines w0.254: -7.417,-23.626 160.223,-23.626 ; -7.417,-18.462 160.274,-18.462 ; -7.417,-13.297 -7.417,-28.791 94.31,-28.791 160.274,-28.791 160.274,-13.297 -7.404,-13.297 -7.404,-28.791 32.614,-28.791 ; 55.194,-28.791 55.194,-13.297 ; 87.376,-18.462 87.376,-13.297 ; 108.712,-18.462 108.712,-13.297 ; 124.511,-28.956 124.511,-23.804
  text "ALL ARTWORK VIEWED FROM TOP SIDE" at -5.804,-16.654 h1.52
  text "BOARD #:" at 57.099,-16.654 h1.52
  text ".PRJ_Number" at 70.955,-16.654 h1.52
  text "REV:" at 92.405,-16.654 h1.52
  text ".PCB_Rev" at 99.809,-16.654 h1.52
  text "SVN REV:" at 113.69,-16.654 h1.52
  text ".VersionControl_RevNumber" at 126.543,-16.654 h1.52
  text "LAYER NAME =" at -5.804,-21.806 h1.52
  text "TID #:" at 57.099,-21.819 h1.52
  text ".TID" at 70.955,-21.819 h1.52
  text "PLOT NAME =" at -5.804,-27.034 h1.52
  text ".plot_File_Name" at 14.656,-27.034 h1.52
  text "GENERATED    :" at 57.15,-27.034 h1.52
  text ".Print_Date" at 79.235,-27.034 h1.52
  text ".Print_Time" at 97.752,-27.034 h1.52
  text "TEXAS INSTRUMENTS" at 129.87,-27.034 h1.52
M12 Stackup:
  drawing of 503 lines, arcs and shapes, not listed
  text "Layer" at 128.529,165.291 h1.52
  text "Name" at 138.941,165.291 h1.52
  text "Material" at 162.556,165.291 h1.52
  text "Thickness" at 184.394,165.291 h1.52
  text "Constant" at 200.9,165.291 h1.52
  text "Board Layer Stack" at 215.375,165.291 h1.52
  text "1" at 128.529,162.243 h1.52
  text "Top Overlay" at 138.941,162.243 h1.52
  text "2" at 128.529,159.195 h1.52
  text "Top Solder" at 138.941,159.195 h1.52
  text "Solder Resist" at 162.556,159.195 h1.52
  text "0.40mil" at 184.394,159.195 h1.52
  text "3.5" at 200.9,159.195 h1.52
  text "3" at 128.529,156.147 h1.52
  text "Top Layer" at 138.941,156.147 h1.52
  text "Copper" at 162.556,156.147 h1.52
  text "2.76mil" at 184.394,156.147 h1.52
  text "4" at 128.529,153.099 h1.52
  text "Dielectric 1" at 138.941,153.099 h1.52
  text "Core-009" at 162.556,153.099 h1.52
  text "4.00mil" at 184.394,153.099 h1.52
  text "4.5" at 200.9,153.099 h1.52
  text "5" at 128.529,150.051 h1.52
  text "Layer 2" at 138.941,150.051 h1.52
  text "Copper" at 162.556,150.051 h1.52
  text "2.76mil" at 184.394,150.051 h1.52
  text "6" at 128.529,147.003 h1.52
  text "Dielectric 3" at 138.941,147.003 h1.52
  text "Core-009" at 162.556,147.003 h1.52
  text "4.00mil" at 184.394,147.003 h1.52
  text "4.5" at 200.9,147.003 h1.52
  text "7" at 128.529,143.955 h1.52
  text "Layer 3" at 138.941,143.955 h1.52
  text "Copper" at 162.556,143.955 h1.52
  text "2.76mil" at 184.394,143.955 h1.52
  text "8" at 128.529,140.907 h1.52
  text "Dielectric 5" at 138.941,140.907 h1.52
  text "Core-009" at 162.556,140.907 h1.52
  text "4.00mil" at 184.394,140.907 h1.52
  text "4.5" at 200.9,140.907 h1.52
  text "9" at 128.529,137.859 h1.52
  text "Layer 4" at 138.941,137.859 h1.52
  text "Copper" at 162.556,137.859 h1.52
  text "2.76mil" at 184.394,137.859 h1.52
  text "10" at 128.529,134.811 h1.52
  text "Dielectric1" at 138.941,134.811 h1.52
  text "Core-009" at 162.556,134.811 h1.52
  text "4.00mil" at 184.394,134.811 h1.52
  text "4.5" at 200.9,134.811 h1.52
  text "11" at 128.529,131.763 h1.52
  text "Layer 5" at 138.941,131.763 h1.52
  text "Copper" at 162.556,131.763 h1.52
  text "2.76mil" at 184.394,131.763 h1.52
  text "12" at 128.529,128.715 h1.52
  text "Dielectric 6" at 138.941,128.715 h1.52
  text "Core-009" at 162.556,128.715 h1.52
  text "4.00mil" at 184.394,128.715 h1.52
  text "4.5" at 200.9,128.715 h1.52
  text "13" at 128.529,125.667 h1.52
  text "Layer 6" at 138.941,125.667 h1.52
  text "Copper" at 162.556,125.667 h1.52
  text "2.76mil" at 184.394,125.667 h1.52
  text "14" at 128.529,122.619 h1.52
  text "Dielectric 4" at 138.941,122.619 h1.52
  text "Core-009" at 162.556,122.619 h1.52
  text "4.00mil" at 184.394,122.619 h1.52
  text "4.5" at 200.9,122.619 h1.52
  text "15" at 128.529,119.571 h1.52
  text "Layer 7" at 138.941,119.571 h1.52
  text "Copper" at 162.556,119.571 h1.52
  text "2.76mil" at 184.394,119.571 h1.52
  text "16" at 128.529,116.523 h1.52
  text "Dielectric 2" at 138.941,116.523 h1.52
  text "Core-009" at 162.556,116.523 h1.52
  text "4.00mil" at 184.394,116.523 h1.52
  text "4.5" at 200.9,116.523 h1.52
  text "17" at 128.529,113.475 h1.52
  text "Bottom Layer" at 138.941,113.475 h1.52
  text "Copper" at 162.556,113.475 h1.52
  text "2.76mil" at 184.394,113.475 h1.52
  text "18" at 128.529,110.427 h1.52
  text "Bottom Solder" at 138.941,110.427 h1.52
  text "Solder Resist" at 162.556,110.427 h1.52
  text "0.40mil" at 184.394,110.427 h1.52
  text "3.5" at 200.9,110.427 h1.52
  text "19" at 128.529,107.379 h1.52
  text "Bottom Overlay" at 138.941,107.379 h1.52
  text ".Layer_Name" at 14.656,-21.806 h1.52
M13 Component Bodies Top:
  text ".Layer_Name" at 14.656,-21.806 h1.52
M14 Component Bodies Bottom:
  text ".Layer_Name" at 14.656,-21.806 h1.52
M15 Courtyards Top:
  text ".Layer_Name" at 14.656,-21.806 h1.52
M16 Courtyards Bottom:
  text ".Layer_Name" at 14.656,-21.806 h1.52
Drill Drawing:
  circle w0.254: c136.238,80.568 r0.702
  lines w0.254: 135.537,83.024 136.94,83.024 136.94,84.427 135.537,84.427 135.537,83.024
  lines w0.305: 134.264,78.919 216.344,78.919 ; 134.264,85.234 216.344,85.234 ; 142.846,75.761 142.846,88.392 ; 151.279,75.761 151.279,88.392 ; 167.448,75.761 167.448,88.392 ; 174.03,75.761 174.03,88.392 ; 183.559,75.761 183.559,88.392 ; 201.957,75.761 201.957,88.392 ; 134.264,75.761 216.344,75.761 216.344,88.392 134.264,88.392 134.264,75.761
  text "Symbol" at 136.159,86.182 h1.83
  text "Quantity" at 143.793,86.182 h1.83
  text "Finished Hole Size" at 152.226,86.182 h1.83
  text "Plated" at 168.395,86.182 h1.83
  text "Hole Type" at 174.977,86.182 h1.83
  text "Drill Layer Pair" at 184.506,86.182 h1.83
  text "Hole Tolerance" at 202.904,86.182 h1.83
  text "1014" at 143.793,83.024 h1.52
  text "8.00mil (0.203mm)" at 152.226,83.024 h1.52
  text "PTH" at 168.395,83.024 h1.52
  text "Round" at 174.977,83.024 h1.52
  text "Top Layer - Bottom Layer" at 184.506,83.024 h1.52
  text "1" at 143.793,79.866 h1.52
  text "10.00mil (0.254mm)" at 152.226,79.866 h1.52
  text "PTH" at 168.395,79.866 h1.52
  text "Round" at 174.977,79.866 h1.52
  text "Top Layer - Bottom Layer" at 184.506,79.866 h1.52
  text "1015 Total" at 143.793,76.708 h1.52
  text ".Layer_Name" at 14.656,-21.806 h1.52
M17 Embedded Cavity:
  text ".Layer_Name" at 14.656,-21.806 h1.52
M18 Embedded Assembly:
  text ".Layer_Name" at 14.656,-21.806 h1.52
M19 Embedded Keepout:
  text ".Layer_Name" at 14.656,-21.806 h1.52

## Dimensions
0,0 to 5.258,0.127 on M2 Board Dimensions
0,0 to 5.256,0.152 on M2 Board Dimensions
0,-10.16 to 25.4,-10.16 on M2 Board Dimensions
